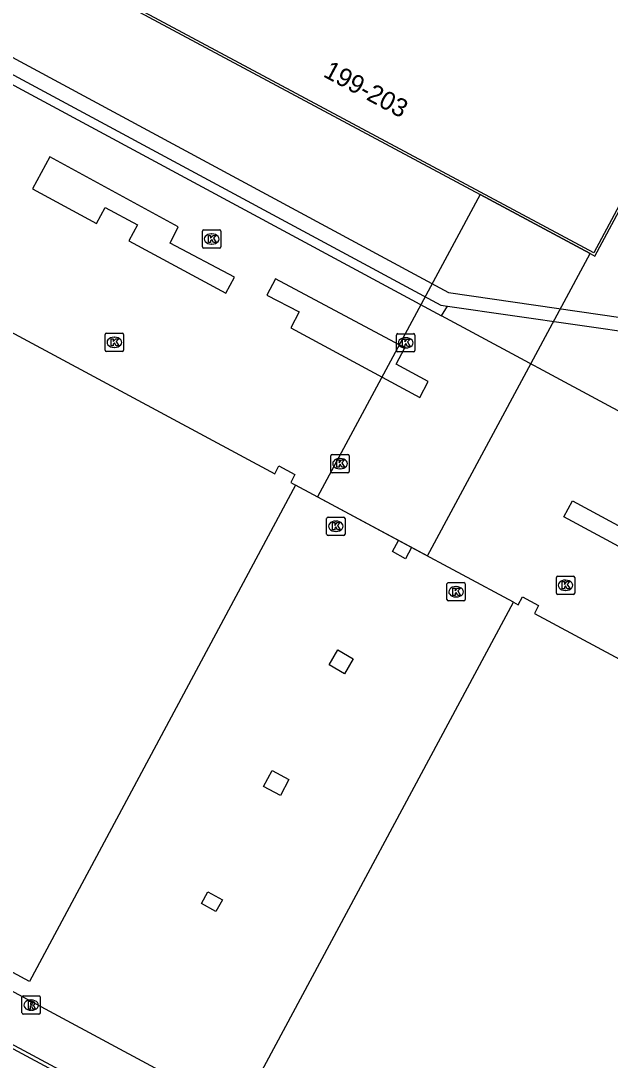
# Model space of a CAD drawing. Extents: x 159489 to 160304, y 383826 to 384530.
# Drawn here: x 159703.5 to 159735.7, y 384278.1 to 384334.8 of the extents above; entities that cross this region are included whole.
import ezdxf

# ---------------------------------------------------------------- set-up
doc = ezdxf.new("R2010")
doc.units = 0
for name, color, linetype in [('IMGEO_Dek', 7, 'Continuous'), ('IMGEO_Kolk', 7, 'Continuous'), ('IMGEO_Lijnafwatering', 7, 'Continuous'), ('IMGEO_Pand', 7, 'Continuous'), ('IMGEO_Pand_nummerreeks', 7, 'Continuous'), ('IMGEO_Pand_overbouw', 7, 'Continuous'), ('IMGEO_Rioolput', 7, 'Continuous'), ('IMGEO_Voetpad_gesloten', 7, 'Continuous'), ('IMGEO_Voetpad_open', 7, 'Continuous')]:
    doc.layers.add(name, color=color, linetype=linetype)

msp = doc.modelspace()

# ---------------------------------------------------------------- linework, layer by layer
at = {"layer": 'IMGEO_Dek'}
msp.add_lwpolyline([(159734.596, 384322.101), (159728.589, 384325.319), (159719.719, 384308.817), (159725.721, 384305.59)], close=True, dxfattribs=at)
at = {"layer": 'IMGEO_Kolk'}
for p, q in [((159713.436, 384322.465), (159713.436, 384323.317)), ((159713.511, 384323.391), (159714.363, 384323.391)), ((159714.437, 384323.317), (159714.437, 384322.465)), ((159713.924, 384323.171), (159713.949, 384323.171)), ((159714.363, 384322.391), (159713.511, 384322.391)), ((159713.947, 384322.611), (159713.922, 384322.611)), ((159708.125, 384316.825), (159708.125, 384317.677)), ((159708.2, 384317.751), (159709.052, 384317.751)), ((159709.126, 384317.677), (159709.126, 384316.825)), ((159724.028, 384316.798), (159724.028, 384317.65)), ((159724.103, 384317.724), (159724.955, 384317.724)), ((159725.029, 384317.65), (159725.029, 384316.798)), ((159708.613, 384317.531), (159708.638, 384317.531)), ((159724.516, 384317.504), (159724.541, 384317.504)), ((159709.052, 384316.751), (159708.2, 384316.751)), ((159708.636, 384316.971), (159708.611, 384316.971)), ((159724.955, 384316.724), (159724.103, 384316.724)), ((159724.539, 384316.944), (159724.514, 384316.944)), ((159720.445, 384310.206), (159720.445, 384311.058)), ((159720.52, 384311.132), (159721.372, 384311.132)), ((159720.933, 384310.912), (159720.958, 384310.912)), ((159721.446, 384311.058), (159721.446, 384310.206)), ((159720.956, 384310.352), (159720.931, 384310.352)), ((159721.372, 384310.132), (159720.52, 384310.132)), ((159720.214, 384306.786), (159720.214, 384307.638)), ((159720.289, 384307.712), (159721.141, 384307.712)), ((159720.702, 384307.492), (159720.727, 384307.492)), ((159721.215, 384307.638), (159721.215, 384306.786)), ((159720.725, 384306.932), (159720.7, 384306.932)), ((159721.141, 384306.712), (159720.289, 384306.712)), ((159726.779, 384303.211), (159726.779, 384304.063)), ((159726.854, 384304.137), (159727.706, 384304.137)), ((159727.78, 384304.063), (159727.78, 384303.211)), ((159732.752, 384303.565), (159732.752, 384304.417)), ((159732.827, 384304.491), (159733.679, 384304.491)), ((159733.24, 384304.271), (159733.265, 384304.271)), ((159733.753, 384304.417), (159733.753, 384303.565)), ((159727.267, 384303.917), (159727.292, 384303.917)), ((159733.679, 384303.491), (159732.827, 384303.491)), ((159733.263, 384303.711), (159733.238, 384303.711)), ((159727.706, 384303.137), (159726.854, 384303.137)), ((159727.29, 384303.357), (159727.265, 384303.357))]:
    msp.add_line(p, q, dxfattribs=at)
for points in [[(159713.436, 384322.465), (159713.436, 384323.317)], [(159713.511, 384323.391), (159714.363, 384323.391)], [(159714.437, 384323.317), (159714.437, 384322.465)], [(159713.757, 384323.091), (159713.88, 384323.091), (159713.88, 384322.94), (159714.01, 384323.091), (159714.174, 384323.091), (159714.028, 384322.94), (159714.181, 384322.691), (159714.029, 384322.691), (159713.944, 384322.855), (159713.88, 384322.788), (159713.88, 384322.691), (159713.757, 384322.691), (159713.757, 384323.091)], [(159714.363, 384322.391), (159713.511, 384322.391)], [(159708.125, 384316.825), (159708.125, 384317.677)], [(159708.2, 384317.751), (159709.052, 384317.751)], [(159709.126, 384317.677), (159709.126, 384316.825)], [(159724.028, 384316.798), (159724.028, 384317.65)], [(159724.103, 384317.724), (159724.955, 384317.724)], [(159725.029, 384317.65), (159725.029, 384316.798)], [(159708.446, 384317.451), (159708.569, 384317.451), (159708.569, 384317.3), (159708.699, 384317.451), (159708.863, 384317.451), (159708.717, 384317.3), (159708.87, 384317.051), (159708.718, 384317.051), (159708.633, 384317.215), (159708.569, 384317.148), (159708.569, 384317.051), (159708.446, 384317.051), (159708.446, 384317.451)], [(159724.349, 384317.424), (159724.472, 384317.424), (159724.472, 384317.273), (159724.602, 384317.424), (159724.766, 384317.424), (159724.62, 384317.273), (159724.773, 384317.024), (159724.621, 384317.024), (159724.536, 384317.188), (159724.472, 384317.121), (159724.472, 384317.024), (159724.349, 384317.024), (159724.349, 384317.424)], [(159709.052, 384316.751), (159708.2, 384316.751)], [(159724.955, 384316.724), (159724.103, 384316.724)], [(159720.445, 384310.206), (159720.445, 384311.058)], [(159720.52, 384311.132), (159721.372, 384311.132)], [(159720.766, 384310.832), (159720.889, 384310.832), (159720.889, 384310.681), (159721.019, 384310.832), (159721.183, 384310.832), (159721.037, 384310.681), (159721.19, 384310.432), (159721.038, 384310.432), (159720.953, 384310.596), (159720.889, 384310.529), (159720.889, 384310.432), (159720.766, 384310.432), (159720.766, 384310.832)], [(159721.446, 384311.058), (159721.446, 384310.206)], [(159721.372, 384310.132), (159720.52, 384310.132)], [(159720.214, 384306.786), (159720.214, 384307.638)], [(159720.289, 384307.712), (159721.141, 384307.712)], [(159720.535, 384307.412), (159720.658, 384307.412), (159720.658, 384307.261), (159720.788, 384307.412), (159720.952, 384307.412), (159720.806, 384307.261), (159720.959, 384307.012), (159720.807, 384307.012), (159720.722, 384307.176), (159720.658, 384307.109), (159720.658, 384307.012), (159720.535, 384307.012), (159720.535, 384307.412)], [(159721.215, 384307.638), (159721.215, 384306.786)], [(159721.141, 384306.712), (159720.289, 384306.712)], [(159726.779, 384303.211), (159726.779, 384304.063)], [(159726.854, 384304.137), (159727.706, 384304.137)], [(159727.78, 384304.063), (159727.78, 384303.211)], [(159732.752, 384303.565), (159732.752, 384304.417)], [(159732.827, 384304.491), (159733.679, 384304.491)], [(159733.073, 384304.191), (159733.196, 384304.191), (159733.196, 384304.04), (159733.326, 384304.191), (159733.49, 384304.191), (159733.344, 384304.04), (159733.497, 384303.791), (159733.345, 384303.791), (159733.26, 384303.955), (159733.196, 384303.888), (159733.196, 384303.791), (159733.073, 384303.791), (159733.073, 384304.191)], [(159733.753, 384304.417), (159733.753, 384303.565)], [(159727.1, 384303.837), (159727.223, 384303.837), (159727.223, 384303.686), (159727.353, 384303.837), (159727.517, 384303.837), (159727.371, 384303.686), (159727.524, 384303.437), (159727.372, 384303.437), (159727.287, 384303.601), (159727.223, 384303.534), (159727.223, 384303.437), (159727.1, 384303.437), (159727.1, 384303.837)], [(159733.679, 384303.491), (159732.827, 384303.491)], [(159727.706, 384303.137), (159726.854, 384303.137)]]:
    msp.add_lwpolyline(points, dxfattribs=at)
for centre, start, end in [((159713.513, 384323.315), 91.552, 178.448), ((159713.513, 384323.315), 91.552, 178.448), ((159714.361, 384323.315), 1.552, 88.448), ((159714.361, 384323.315), 1.552, 88.448), ((159713.513, 384322.467), 181.552, 268.448), ((159713.513, 384322.467), 181.552, 268.448), ((159714.361, 384322.467), 271.552, 358.448), ((159714.361, 384322.467), 271.552, 358.448), ((159708.202, 384317.675), 91.552, 178.448), ((159708.202, 384317.675), 91.552, 178.448), ((159709.05, 384317.675), 1.552, 88.448), ((159709.05, 384317.675), 1.552, 88.448), ((159724.105, 384317.648), 91.552, 178.448), ((159724.105, 384317.648), 91.552, 178.448), ((159724.953, 384317.648), 1.552, 88.448), ((159724.953, 384317.648), 1.552, 88.448), ((159708.202, 384316.827), 181.552, 268.448), ((159708.202, 384316.827), 181.552, 268.448), ((159709.05, 384316.827), 271.552, 358.448), ((159709.05, 384316.827), 271.552, 358.448), ((159724.105, 384316.8), 181.552, 268.448), ((159724.105, 384316.8), 181.552, 268.448), ((159724.953, 384316.8), 271.552, 358.448), ((159724.953, 384316.8), 271.552, 358.448), ((159720.522, 384311.056), 91.552, 178.448), ((159720.522, 384311.056), 91.552, 178.448), ((159721.37, 384311.056), 1.552, 88.448), ((159721.37, 384311.056), 1.552, 88.448), ((159720.522, 384310.208), 181.552, 268.448), ((159720.522, 384310.208), 181.552, 268.448), ((159721.37, 384310.208), 271.552, 358.448), ((159721.37, 384310.208), 271.552, 358.448), ((159720.291, 384307.636), 91.552, 178.448), ((159720.291, 384307.636), 91.552, 178.448), ((159721.139, 384307.636), 1.552, 88.448), ((159721.139, 384307.636), 1.552, 88.448), ((159720.291, 384306.788), 181.552, 268.448), ((159720.291, 384306.788), 181.552, 268.448), ((159721.139, 384306.788), 271.552, 358.448), ((159721.139, 384306.788), 271.552, 358.448), ((159726.856, 384304.061), 91.552, 178.448), ((159726.856, 384304.061), 91.552, 178.448), ((159727.704, 384304.061), 1.552, 88.448), ((159727.704, 384304.061), 1.552, 88.448), ((159732.829, 384304.415), 91.552, 178.448), ((159732.829, 384304.415), 91.552, 178.448), ((159733.677, 384304.415), 1.552, 88.448), ((159733.677, 384304.415), 1.552, 88.448), ((159732.829, 384303.567), 181.552, 268.448), ((159732.829, 384303.567), 181.552, 268.448), ((159733.677, 384303.567), 271.552, 358.448), ((159733.677, 384303.567), 271.552, 358.448), ((159726.856, 384303.213), 181.552, 268.448), ((159726.856, 384303.213), 181.552, 268.448), ((159727.704, 384303.213), 271.552, 358.448), ((159727.704, 384303.213), 271.552, 358.448)]:
    msp.add_arc(centre, 0.0765, start, end, dxfattribs=at)
for centre, major_axis, ratio, start_param, end_param in [((159713.923, 384322.891), (-0.387, 0.002), 0.722429, 4.712389, 7.853982), ((159713.948, 384322.891), (-0.39, 0.002), 0.717154, 1.570796, 4.712389), ((159708.612, 384317.251), (-0.387, 0.002), 0.722429, 4.712389, 7.853982), ((159708.637, 384317.251), (-0.39, 0.002), 0.717154, 1.570796, 4.712389), ((159724.515, 384317.224), (-0.387, 0.002), 0.722429, 4.712389, 7.853982), ((159724.54, 384317.224), (-0.39, 0.002), 0.717154, 1.570796, 4.712389), ((159720.932, 384310.632), (-0.387, 0.002), 0.722429, 4.712389, 7.853982), ((159720.957, 384310.632), (-0.39, 0.002), 0.717154, 1.570796, 4.712389), ((159720.701, 384307.212), (-0.387, 0.002), 0.722429, 4.712389, 7.853982), ((159720.726, 384307.212), (-0.39, 0.002), 0.717154, 1.570796, 4.712389), ((159733.239, 384303.991), (-0.387, 0.002), 0.722429, 4.712389, 7.853982), ((159733.264, 384303.991), (-0.39, 0.002), 0.717154, 1.570796, 4.712389), ((159727.266, 384303.637), (-0.387, 0.002), 0.722429, 4.712389, 7.853982), ((159727.291, 384303.637), (-0.39, 0.002), 0.717154, 1.570796, 4.712389)]:
    msp.add_ellipse(centre, major_axis=major_axis, ratio=ratio, start_param=start_param, end_param=end_param, dxfattribs=at)
at = {"layer": 'IMGEO_Lijnafwatering'}
msp.add_lwpolyline([(159711.214, 384274.544), (159694.446, 384283.552)], dxfattribs=at)
at = {"layer": 'IMGEO_Pand'}
for points in [[(159744.117, 384339.565), (159734.794, 384322.143), (159708.49, 384336.235), (159717.843, 384353.7)], [(159693.74, 384322.781), (159717.376, 384310.076), (159717.604, 384310.502), (159718.485, 384310.029), (159718.256, 384309.603), (159718.52, 384309.461)], [(159718.52, 384309.461), (159703.988, 384282.369), (159693.529, 384288.01), (159693.055, 384287.196), (159693.021, 384287.138), (159678.693, 384294.844)], [(159779.824, 384240.489), (159765.546, 384248.161), (159765.572, 384248.208), (159766.025, 384249.054), (159715.868, 384275.99), (159730.406, 384303.072)], [(159730.406, 384303.072), (159730.67, 384302.93), (159730.898, 384303.355), (159731.779, 384302.882), (159731.551, 384302.457), (159747.439, 384293.915), (159794.673, 384268.525)], [(159721.19, 384299.162), (159720.343, 384299.654), (159720.815, 384300.466), (159721.661, 384299.975), (159721.19, 384299.162)], [(159717.688, 384292.525), (159716.775, 384293.016), (159717.236, 384293.874), (159718.149, 384293.384), (159717.688, 384292.525)], [(159714.163, 384286.183), (159713.378, 384286.626), (159713.736, 384287.261), (159714.521, 384286.819), (159714.163, 384286.183)]]:
    msp.add_lwpolyline(points, dxfattribs=at)
at = {"layer": 'IMGEO_Pand_overbouw'}
for points in [[(159772.845, 384392.873), (159746.364, 384407.132), (159719.057, 384356.211), (159708.316, 384336.181), (159708.428, 384336.121), (159728.589, 384325.319), (159734.596, 384322.101), (159734.859, 384321.96), (159745.598, 384342.008)], [(159745.463, 384342.08), (159744.495, 384340.27), (159744.117, 384339.565), (159734.794, 384322.143), (159708.49, 384336.235), (159717.843, 384353.7), (159718.221, 384354.406), (159719.159, 384356.157)], [(159718.52, 384309.461), (159703.988, 384282.369), (159693.529, 384288.01), (159693.055, 384287.196), (159765.572, 384248.208), (159766.025, 384249.054), (159715.868, 384275.99), (159730.406, 384303.072), (159724.846, 384306.056), (159724.134, 384306.443)]]:
    msp.add_lwpolyline(points, close=True, dxfattribs=at)
at = {"layer": 'IMGEO_Rioolput'}
for p, q in [((159703.583, 384280.651), (159703.583, 384281.503)), ((159703.658, 384281.577), (159704.51, 384281.577)), ((159704.071, 384281.357), (159704.096, 384281.357)), ((159704.584, 384281.503), (159704.584, 384280.651)), ((159704.094, 384280.797), (159704.069, 384280.797)), ((159704.51, 384280.577), (159703.658, 384280.577))]:
    msp.add_line(p, q, dxfattribs=at)
for points in [[(159703.583, 384280.651), (159703.583, 384281.503)], [(159703.658, 384281.577), (159704.51, 384281.577)], [(159704.584, 384281.503), (159704.584, 384280.651)], [(159704.172, 384281.275), (159703.92, 384281.277), (159703.92, 384280.877)], [(159703.92, 384280.877), (159704.044, 384280.877), (159704.044, 384281.039), (159704.055, 384281.039)], [(159704.098, 384281.196), (159704.044, 384281.196), (159704.044, 384281.115)], [(159704.044, 384281.115), (159704.096, 384281.115)], [(159704.102, 384281.01), (159704.173, 384280.877), (159704.313, 384280.877), (159704.248, 384281.003)], [(159704.51, 384280.577), (159703.658, 384280.577)]]:
    msp.add_lwpolyline(points, dxfattribs=at)
for centre, radius, start, end in [((159703.66, 384281.501), 0.0765, 91.552, 178.448), ((159703.66, 384281.501), 0.0765, 91.552, 178.448), ((159704.508, 384281.501), 0.0765, 1.552, 88.448), ((159704.508, 384281.501), 0.0765, 1.552, 88.448), ((159704.054, 384280.986), 0.0533, 26.0293, 88.6989), ((159704.08, 384281.304), 0.19, 274.7715, 282.9687), ((159704.104, 384281.1), 0.0964, 77.0061, 93.1865), ((159704.118, 384281.157), 0.0378, 276.6634, 79.6772), ((159704.171, 384281.165), 0.109, 350.3612, 89.416), ((159704.169, 384281.165), 0.112, 277.5842, 350.9817), ((159704.153, 384280.95), 0.108, 29.5134, 73.7905), ((159703.66, 384280.653), 0.0765, 181.552, 268.448), ((159703.66, 384280.653), 0.0765, 181.552, 268.448), ((159704.508, 384280.653), 0.0765, 271.552, 358.448), ((159704.508, 384280.653), 0.0765, 271.552, 358.448)]:
    msp.add_arc(centre, radius, start, end, dxfattribs=at)
for centre, major_axis, ratio, start_param, end_param in [((159704.07, 384281.077), (-0.387, 0.002), 0.722429, 4.712389, 7.853982), ((159704.095, 384281.077), (-0.39, 0.002), 0.717154, 1.570796, 4.712389)]:
    msp.add_ellipse(centre, major_axis=major_axis, ratio=ratio, start_param=start_param, end_param=end_param, dxfattribs=at)
at = {"layer": 'IMGEO_Voetpad_gesloten'}
for points in [[(159717.843, 384353.7), (159712.762, 384356.443), (159700.707, 384334.064), (159726.866, 384319.977), (159741.046, 384317.91), (159797.007, 384309.896), (159800.092, 384309.462), (159781.262, 384319.609), (159744.117, 384339.565)], [(159734.596, 384322.101), (159728.589, 384325.319), (159719.719, 384308.817), (159725.721, 384305.59), (159734.596, 384322.101)]]:
    msp.add_lwpolyline(points, dxfattribs=at)
at = {"layer": 'IMGEO_Voetpad_open'}
for points in [[(159712.442, 384357.532), (159699.61, 384333.72), (159726.44, 384319.286), (159726.801, 384319.234)], [(159699.381, 384333.281), (159726.485, 384318.691)], [(159705.101, 384327.367), (159704.159, 384325.622), (159707.658, 384323.74), (159708.13, 384324.61), (159709.88, 384323.672), (159709.423, 384322.784), (159714.71, 384319.933), (159715.178, 384320.807), (159711.668, 384322.666), (159712.108, 384323.561), (159705.101, 384327.367)], [(159724.481, 384316.952), (159717.417, 384320.724), (159716.952, 384319.819), (159718.713, 384318.921), (159718.256, 384318.05), (159725.298, 384314.239), (159725.754, 384315.114), (159724.004, 384316.059), (159724.481, 384316.952)], [(159726.485, 384318.691), (159726.801, 384319.234)], [(159726.801, 384319.234), (159741.002, 384317.183), (159741.576, 384317.086)], [(159736.839, 384313.125), (159726.485, 384318.691)], [(159730.406, 384303.072), (159724.846, 384306.056), (159724.517, 384305.443), (159723.803, 384305.826), (159724.134, 384306.443), (159718.52, 384309.461)], [(159733.627, 384308.609), (159742.427, 384303.848), (159741.96, 384302.978), (159733.153, 384307.722), (159733.627, 384308.609)], [(159778.522, 384238.137), (159775.75, 384232.935), (159674.737, 384287.233), (159677.536, 384292.428), (159778.522, 384238.137)]]:
    msp.add_lwpolyline(points, dxfattribs=at)

# ---------------------------------------------------------------- texts
at = {"layer": 'IMGEO_Pand_nummerreeks'}
msp.add_text('199-203', height=1, rotation=331.8219, dxfattribs=at).set_placement((159719.969, 384331.787))

doc.saveas('drawing.dxf')
